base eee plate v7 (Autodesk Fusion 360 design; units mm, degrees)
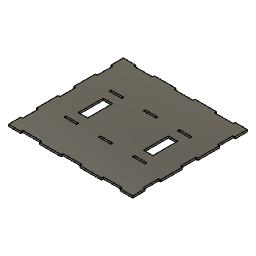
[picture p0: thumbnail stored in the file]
sketch "Sketch1" plane through (0, 0, 0) normal (0, 0, 1) x axis (1, 0, 0)
  line L1 (-100, 92.5) -> (100, 92.5)
  line L2 (-100, -92.5) -> (-100, 92.5)
  line L3 (100, -92.5) -> (-100, -92.5)
  line L4 (100, 92.5) -> (100, -92.5)
  line L5 (-100, -92.5) -> (100, 92.5)
  line L6 (100, -92.5) -> (-100, 92.5)
  point P6 (0, 0)
  point P1 (0, 0)
  point P4 (-100, -92.5)
  point P5 (100, -92.5)
  point P3 (-100, 92.5)
  perpendicular L1 L2
  parallel L1 L3
  parallel L2 L4
  horizontal L1
  coincident L5 P6
  coincident L6 P6
  coincident P1 P6
  dimension "d1" distance P4 P5 = 200
  dimension "d2" distance P3 P4 = 185
extrude "Extrude1" new body sketch "Sketch1" profile of L1 L2 L3 L4 along normal blind 3
sketch "Sketch2" plane through (0, 0, 3) normal (0, 0, 1) x axis (-1, 0, 0)
  line L1 (-100, -92.5) -> (-100, 92.5)
  line L2 (100, -92.5) -> (-100, -92.5)
  line L3 (100, 92.5) -> (100, -92.5)
  line L4 (-100, 92.5) -> (100, 92.5)
  line L5 (75, 37.75) -> (-75, 37.75)
  line L6 (75, -37.75) -> (75, 37.75)
  line L7 (-75, -37.75) -> (75, -37.75)
  line L8 (-75, 37.75) -> (-75, -37.75)
  line L9 (75, -37.75) -> (-75, 37.75)
  line L10 (-75, -37.75) -> (75, 37.75)
  line L11 (45, -37.75) -> (65, -37.75)
  line L12 (45, -34.75) -> (45, -37.75)
  line L13 (65, -34.75) -> (45, -34.75)
  line L14 (65, -37.75) -> (65, -34.75)
  line L15 (-10, -37.75) -> (10, -37.75)
  line L16 (-10, -34.75) -> (-10, -37.75)
  line L17 (10, -34.75) -> (-10, -34.75)
  line L18 (10, -37.75) -> (10, -34.75)
  line L19 (-65, -37.75) -> (-45, -37.75)
  line L20 (-65, -34.75) -> (-65, -37.75)
  line L21 (-45, -34.75) -> (-65, -34.75)
  line L22 (-45, -37.75) -> (-45, -34.75)
  point P10 (0, 0)
  point P1 (0, 0)
  point P11 (65, -37.75)
  point P15 (10, -37.75)
  point P19 (-45, -37.75)
  point P8 (75, -37.75)
  point P9 (-75, -37.75)
  point P7 (75, 37.75)
  point P12 (45, -37.75)
  point P13 (45, -34.75)
  point P16 (-10, -37.75)
  point P20 (-65, -37.75)
  perpendicular L5 L6
  parallel L5 L7
  parallel L6 L8
  horizontal L5
  coincident L9 P10
  coincident L10 P10
  coincident P1 P10
  horizontal L11
  vertical L12
  horizontal L13
  vertical L14
  coincident L7 P11
  horizontal L15
  vertical L16
  horizontal L17
  vertical L18
  coincident L7 P15
  horizontal L19
  vertical L20
  horizontal L21
  vertical L22
  coincident L7 P19
  equal L14 L18
  equal L18 L22
  dimension "d5" distance P8 P9 = 150
  dimension "d6" distance P7 P8 = 75.5
  dimension "d7" distance L6 L14 = 10
  dimension "d8" distance L7 L13 = 3
  dimension "d9" distance P11 P12 = 20
  dimension "d10" distance P13 L18 = 35
  dimension "d11" distance P15 P16 = 20
  dimension "d12" distance L16 P19 = 35
  dimension "d13" distance L8 L20 = 10
  dimension "d14" distance P19 P20 = 20
extrude "Extrude2" cut sketch "Sketch2" profile of L11 L12 L13 L14 L15 L16 L17 L18 L19 L20 L21 L22 to an object
mirror "Mirror1"
sketch "Sketch4" plane through (0, 0, 3) normal (0, 0, 1) x axis (-1, 0, 0)
  line L1 (45, 37.75) -> (45, 34.75)
  line L2 (65, 37.75) -> (45, 37.75)
  line L3 (65, 34.75) -> (65, 37.75)
  line L4 (45, 34.75) -> (65, 34.75)
  line L5 (-10, 37.75) -> (-10, 34.75)
  line L6 (10, 37.75) -> (-10, 37.75)
  line L7 (10, 34.75) -> (10, 37.75)
  line L8 (-10, 34.75) -> (10, 34.75)
  line L9 (-65, 37.75) -> (-65, 34.75)
  line L10 (-45, 37.75) -> (-65, 37.75)
  line L11 (-45, 34.75) -> (-45, 37.75)
  line L12 (-65, 34.75) -> (-45, 34.75)
  line L13 (65, -37.75) -> (65, -34.75)
  line L14 (45, -37.75) -> (65, -37.75)
  line L15 (45, -34.75) -> (45, -37.75)
  line L16 (65, -34.75) -> (45, -34.75)
  line L17 (10, -37.75) -> (10, -34.75)
  line L18 (-10, -37.75) -> (10, -37.75)
  line L19 (-10, -34.75) -> (-10, -37.75)
  line L20 (10, -34.75) -> (-10, -34.75)
  line L21 (-45, -37.75) -> (-45, -34.75)
  line L22 (-65, -37.75) -> (-45, -37.75)
  line L23 (-65, -34.75) -> (-65, -37.75)
  line L24 (-45, -34.75) -> (-65, -34.75)
  line L25 (-100, -92.5) -> (-100, 92.5)
  line L26 (100, -92.5) -> (-100, -92.5)
  line L27 (100, 92.5) -> (100, -92.5)
  line L28 (-100, 92.5) -> (100, 92.5)
  line L29 (50, 92.5) -> (80, 92.5)
  line L30 (50, 89.5) -> (50, 92.5)
  line L31 (80, 89.5) -> (50, 89.5)
  line L32 (80, 92.5) -> (80, 89.5)
  line L33 (-15, 92.5) -> (15, 92.5)
  line L34 (-15, 89.5) -> (-15, 92.5)
  line L35 (15, 89.5) -> (-15, 89.5)
  line L36 (15, 92.5) -> (15, 89.5)
  line L37 (-80, 92.5) -> (-50, 92.5)
  line L38 (-80, 89.5) -> (-80, 92.5)
  line L39 (-50, 89.5) -> (-80, 89.5)
  line L40 (-50, 92.5) -> (-50, 89.5)
  line L41 (15, 91) -> (50, 91)
  line L42 (-50, 91) -> (-15, 91)
  point P30 (80, 92.5)
  point P34 (15, 92.5)
  point P38 (-50, 92.5)
  point P42 (50, 91)
  point P43 (15, 91)
  point P44 (-15, 91)
  point P45 (-50, 91)
  point P40 (-80, 89.5)
  point P41 (-50, 89.5)
  point P36 (-15, 89.5)
  point P37 (15, 89.5)
  point P32 (50, 89.5)
  point P33 (80, 89.5)
  horizontal L29
  vertical L30
  horizontal L31
  vertical L32
  coincident L28 P30
  horizontal L33
  vertical L34
  horizontal L35
  vertical L36
  coincident L28 P34
  horizontal L37
  vertical L38
  horizontal L39
  vertical L40
  coincident L28 P38
  equal L32 L36
  equal L36 L40
  midpoint L30 P42
  midpoint L36 P43
  midpoint L34 P44
  midpoint L40 P45
  equal L41 L42
  dimension "d18" distance L29 L31 = 3
  dimension "d19" distance L27 L32 = 20
  dimension "d20" distance L25 L38 = 20
  dimension "d21" distance P40 P41 = 30
  dimension "d22" distance P36 P37 = 30
  dimension "d23" distance P32 P33 = 30
extrude "Extrude3" cut sketch "Sketch4" profile of L21 L28 L29 L30 L31 L32 L33 L34 L35 L36 L37 L38 L39 L40 to an object
mirror "Mirror2"
sketch "Sketch5" plane through (0, 0, 3) normal (0, 0, 1) x axis (-1, 0, 0)
  line L1 (-45, -37.75) -> (-45, -34.75)
  line L2 (-65, -37.75) -> (-45, -37.75)
  line L3 (-65, -34.75) -> (-65, -37.75)
  line L4 (-45, -34.75) -> (-65, -34.75)
  line L5 (10, -37.75) -> (10, -34.75)
  line L6 (-10, -37.75) -> (10, -37.75)
  line L7 (-10, -34.75) -> (-10, -37.75)
  line L8 (10, -34.75) -> (-10, -34.75)
  line L9 (65, -37.75) -> (65, -34.75)
  line L10 (45, -37.75) -> (65, -37.75)
  line L11 (45, -34.75) -> (45, -37.75)
  line L12 (65, -34.75) -> (45, -34.75)
  line L13 (-65, 37.75) -> (-65, 34.75)
  line L14 (-45, 37.75) -> (-65, 37.75)
  line L15 (-45, 34.75) -> (-45, 37.75)
  line L16 (-65, 34.75) -> (-45, 34.75)
  line L17 (-10, 37.75) -> (-10, 34.75)
  line L18 (10, 37.75) -> (-10, 37.75)
  line L19 (10, 34.75) -> (10, 37.75)
  line L20 (-10, 34.75) -> (10, 34.75)
  line L21 (45, 37.75) -> (45, 34.75)
  line L22 (65, 37.75) -> (45, 37.75)
  line L23 (65, 34.75) -> (65, 37.75)
  line L24 (45, 34.75) -> (65, 34.75)
  line L25 (50, -89.5) -> (50, -92.5)
  line L26 (80, -89.5) -> (50, -89.5)
  line L27 (80, -92.5) -> (80, -89.5)
  line L28 (100, -92.5) -> (80, -92.5)
  line L29 (100, 92.5) -> (100, -92.5)
  line L30 (80, 92.5) -> (100, 92.5)
  line L31 (80, 89.5) -> (80, 92.5)
  line L32 (50, 89.5) -> (80, 89.5)
  line L33 (50, 92.5) -> (50, 89.5)
  line L34 (15, 92.5) -> (50, 92.5)
  line L35 (15, 89.5) -> (15, 92.5)
  line L36 (-15, 89.5) -> (15, 89.5)
  line L37 (-15, 92.5) -> (-15, 89.5)
  line L38 (-50, 92.5) -> (-15, 92.5)
  line L39 (-50, 89.5) -> (-50, 92.5)
  line L40 (-80, 89.5) -> (-50, 89.5)
  line L41 (-80, 92.5) -> (-80, 89.5)
  line L42 (-100, 92.5) -> (-80, 92.5)
  line L43 (-100, -92.5) -> (-100, 92.5)
  line L44 (-80, -92.5) -> (-100, -92.5)
  line L45 (-80, -89.5) -> (-80, -92.5)
  line L46 (-50, -89.5) -> (-80, -89.5)
  line L47 (-50, -92.5) -> (-50, -89.5)
  line L48 (-15, -92.5) -> (-50, -92.5)
  line L49 (-15, -89.5) -> (-15, -92.5)
  line L50 (15, -89.5) -> (-15, -89.5)
  line L51 (15, -92.5) -> (15, -89.5)
  line L52 (50, -92.5) -> (15, -92.5)
  line L53 (97, -72.5) -> (100, -72.5)
  line L54 (97, -47.5) -> (97, -72.5)
  line L55 (100, -47.5) -> (97, -47.5)
  line L56 (100, -72.5) -> (100, -47.5)
  line L57 (97, -12.5) -> (100, -12.5)
  line L58 (97, 12.5) -> (97, -12.5)
  line L59 (100, 12.5) -> (97, 12.5)
  line L60 (100, -12.5) -> (100, 12.5)
  line L61 (97, 47.5) -> (100, 47.5)
  line L62 (97, 72.5) -> (97, 47.5)
  line L63 (100, 72.5) -> (97, 72.5)
  line L64 (100, 47.5) -> (100, 72.5)
  line L65 (98.5, -12.5) -> (98.5, -47.5)
  line L66 (98.5, 47.5) -> (98.5, 12.5)
  point P54 (100, -72.5)
  point P58 (100, -12.5)
  point P62 (100, 47.5)
  point P66 (98.5, -47.5)
  point P67 (98.5, -12.5)
  point P68 (98.5, 12.5)
  point P69 (98.5, 47.5)
  point P61 (100, 12.5)
  horizontal L53
  vertical L54
  horizontal L55
  vertical L56
  coincident L29 P54
  horizontal L57
  vertical L58
  horizontal L59
  vertical L60
  coincident L29 P58
  horizontal L61
  vertical L62
  horizontal L63
  vertical L64
  coincident L29 P62
  equal L55 L63
  equal L55 L59
  equal L56 L60
  equal L60 L64
  midpoint L55 P66
  midpoint L57 P67
  midpoint L59 P68
  midpoint L61 P69
  equal L65 L66
  dimension "d27" distance L30 L63 = 20
  dimension "d28" distance L28 L53 = 20
  dimension "d29" distance L62 L64 = 3
  dimension "d31" distance P58 P61 = 25
extrude "Extrude4" cut sketch "Sketch5" profile of L29 L53 L54 L55 L56 L57 L58 L59 L60 L61 L62 L63 L64 to an object
sketch "Sketch6" plane through (0, 0, 3) normal (0, 0, 1) x axis (-1, 0, 0)
  line L1 (97, 47.5) -> (100, 47.5)
  line L2 (97, 72.5) -> (97, 47.5)
  line L3 (100, 72.5) -> (97, 72.5)
  line L4 (100, 92.5) -> (100, 72.5)
  line L5 (80, 92.5) -> (100, 92.5)
  line L6 (80, 89.5) -> (80, 92.5)
  line L7 (50, 89.5) -> (80, 89.5)
  line L8 (50, 92.5) -> (50, 89.5)
  line L9 (15, 92.5) -> (50, 92.5)
  line L10 (15, 89.5) -> (15, 92.5)
  line L11 (-15, 89.5) -> (15, 89.5)
  line L12 (-15, 92.5) -> (-15, 89.5)
  line L13 (-50, 92.5) -> (-15, 92.5)
  line L14 (-50, 89.5) -> (-50, 92.5)
  line L15 (-80, 89.5) -> (-50, 89.5)
  line L16 (-80, 92.5) -> (-80, 89.5)
  line L17 (-100, 92.5) -> (-80, 92.5)
  line L18 (-100, -92.5) -> (-100, 92.5)
  line L19 (-80, -92.5) -> (-100, -92.5)
  line L20 (-80, -89.5) -> (-80, -92.5)
  line L21 (-50, -89.5) -> (-80, -89.5)
  line L22 (-50, -92.5) -> (-50, -89.5)
  line L23 (-15, -92.5) -> (-50, -92.5)
  line L24 (-15, -89.5) -> (-15, -92.5)
  line L25 (15, -89.5) -> (-15, -89.5)
  line L26 (15, -92.5) -> (15, -89.5)
  line L27 (50, -92.5) -> (15, -92.5)
  line L28 (50, -89.5) -> (50, -92.5)
  line L29 (80, -89.5) -> (50, -89.5)
  line L30 (80, -92.5) -> (80, -89.5)
  line L31 (100, -92.5) -> (80, -92.5)
  line L32 (100, -72.5) -> (100, -92.5)
  line L33 (97, -72.5) -> (100, -72.5)
  line L34 (97, -47.5) -> (97, -72.5)
  line L35 (100, -47.5) -> (97, -47.5)
  line L36 (100, -12.5) -> (100, -47.5)
  line L37 (97, -12.5) -> (100, -12.5)
  line L38 (97, 12.5) -> (97, -12.5)
  line L39 (100, 12.5) -> (97, 12.5)
  line L40 (100, 47.5) -> (100, 12.5)
  line L41 (45, 37.75) -> (45, 34.75)
  line L42 (65, 37.75) -> (45, 37.75)
  line L43 (65, 34.75) -> (65, 37.75)
  line L44 (45, 34.75) -> (65, 34.75)
  line L45 (-10, 37.75) -> (-10, 34.75)
  line L46 (10, 37.75) -> (-10, 37.75)
  line L47 (10, 34.75) -> (10, 37.75)
  line L48 (-10, 34.75) -> (10, 34.75)
  line L49 (-65, 37.75) -> (-65, 34.75)
  line L50 (-45, 37.75) -> (-65, 37.75)
  line L51 (-45, 34.75) -> (-45, 37.75)
  line L52 (-65, 34.75) -> (-45, 34.75)
  line L53 (65, -37.75) -> (65, -34.75)
  line L54 (45, -37.75) -> (65, -37.75)
  line L55 (45, -34.75) -> (45, -37.75)
  line L56 (65, -34.75) -> (45, -34.75)
  line L57 (10, -37.75) -> (10, -34.75)
  line L58 (-10, -37.75) -> (10, -37.75)
  line L59 (-10, -34.75) -> (-10, -37.75)
  line L60 (10, -34.75) -> (-10, -34.75)
  line L61 (-45, -37.75) -> (-45, -34.75)
  line L62 (-65, -37.75) -> (-45, -37.75)
  line L63 (-65, -34.75) -> (-65, -37.75)
  line L64 (-45, -34.75) -> (-65, -34.75)
  line L65 (45, -20) -> (60, -20)
  line L66 (45, 20) -> (45, -20)
  line L67 (60, 20) -> (45, 20)
  line L68 (60, -20) -> (60, 20)
  line L69 (-60, -20) -> (-45, -20)
  line L70 (-60, 20) -> (-60, -20)
  line L71 (-45, 20) -> (-60, 20)
  line L72 (-45, -20) -> (-45, 20)
  line L73 (45, 0) -> (-45, 0)
  point P74 (-45, 0)
  point P75 (45, 0)
  point P1 (0, 0)
  point P66 (60, -20)
  point P67 (45, -20)
  point P68 (45, 20)
  horizontal L65
  vertical L66
  horizontal L67
  vertical L68
  horizontal L69
  vertical L70
  horizontal L71
  vertical L72
  midpoint L72 P74
  midpoint L66 P75
  perpendicular L66 L73
  coincident P1 L73
  equal L65 L69
  midpoint P1 L73
  equal L66 L72
  dimension "d35" distance L68 L70 = 120
  dimension "d36" distance P66 P67 = 15
  dimension "d37" distance P67 P68 = 40
extrude "Extrude5" cut sketch "Sketch6" profile of L65 L66 L67 L68 L69 L70 L71 L72 to an object
mirror "Mirror3"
